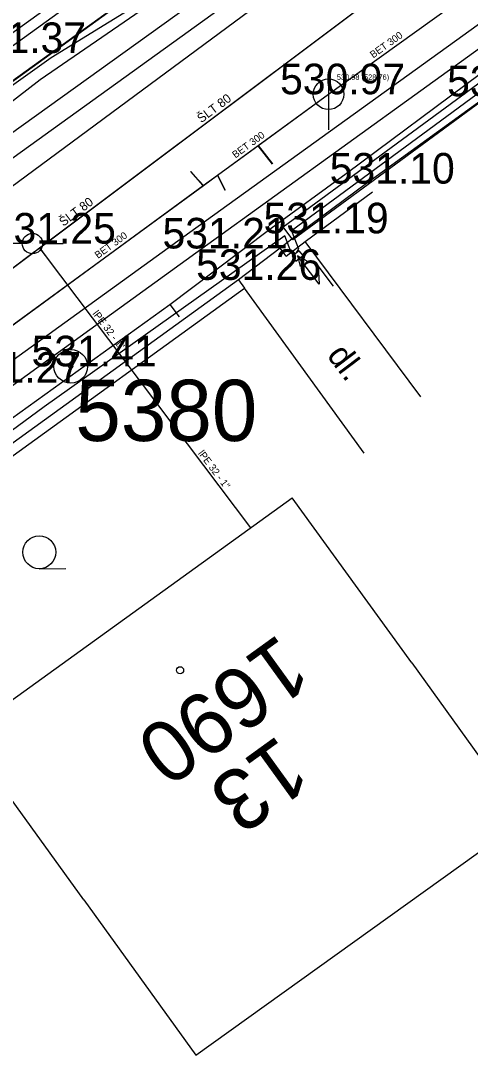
# Model space of a CAD drawing. Extents: x -668867 to -667827, y -1131943 to -1131019.
# Drawn here: x -668744.27 to -668733.24, y -1131426.29 to -1131400.93 of the extents above; entities that cross this region are included whole.
import ezdxf

# ---------------------------------------------------------------- set-up
doc = ezdxf.new("R2010")
doc.units = 0
for name, color, linetype in [('G_Bod_tecka', 7, 'Continuous'), ('G_Bod_vyska', 7, 'Continuous'), ('G_Bodove_pole', 7, 'Continuous'), ('G_Budovy-znacky', 7, 'Continuous'), ('G_Budovy_Objekty', 7, 'Continuous'), ('G_Cesty_Schody', 7, 'Continuous'), ('G_Cisla_orientacni', 7, 'Continuous'), ('G_Cisla_popisna', 7, 'Continuous'), ('G_Plochy_zpevnene', 7, 'Continuous'), ('G_Ploty', 7, 'Continuous'), ('G_Ploty_vstupy', 7, 'Continuous'), ('G_Popisy_povrchu', 7, 'Continuous'), ('G_Site-kanalizace', 7, 'Continuous'), ('G_Site-Rozvadece', 7, 'Continuous'), ('G_Site-vodovod', 7, 'Continuous'), ('G_Z_CHRANICKA-TEPLOVOD_kotovane', 7, 'Continuous'), ('G_Z_ELsilove_podz_kotovane', 7, 'Continuous'), ('G_Z_KANAL_podz_kotovane', 7, 'Continuous'), ('G_Z_PLYNY_podz_geodeticky', 7, 'Continuous'), ('G_Z_SPOJE_podz_geodeticky', 7, 'Continuous'), ('G_Z_SPOJE_podz_kotovane', 7, 'Continuous'), ('G_Z_SPOJE_podz_priblizne', 7, 'Continuous'), ('G_Z_VODA_podz_kotovane', 7, 'Continuous'), ('G_Zelen-Znacky', 7, 'Continuous'), ('Vrstva 10', 7, 'Continuous'), ('Vrstva 13', 7, 'Continuous'), ('Vrstva 17', 7, 'Continuous'), ('Vrstva 2', 7, 'Continuous'), ('Vrstva 25', 7, 'Continuous'), ('Vrstva 26', 7, 'Continuous'), ('Vrstva 3', 7, 'Continuous'), ('Vrstva 4', 7, 'Continuous'), ('Vrstva 6', 7, 'Continuous'), ('Vrstva 8', 7, 'Continuous')]:
    doc.layers.add(name, color=color, linetype=linetype)

msp = doc.modelspace()

# ---------------------------------------------------------------- linework, layer by layer
at = {"layer": 'G_Bod_tecka'}
for p, q in [((-668736.72, -1131402.73), (-668736.72, -1131402.73)), ((-668735.79, -1131404.92), (-668735.79, -1131404.92)), ((-668737.44, -1131406.14), (-668737.44, -1131406.14)), ((-668743.98, -1131406.39), (-668743.98, -1131406.39)), ((-668739.83, -1131406.51), (-668739.83, -1131406.51)), ((-668738.93, -1131407.28), (-668738.93, -1131407.28)), ((-668743.04, -1131409.4), (-668743.04, -1131409.4))]:
    msp.add_line(p, q, dxfattribs=at)
at = {"layer": 'G_Bodove_pole'}
for radius in [0.412, 0.05]:
    msp.add_circle((-668743.04, -1131409.4), radius, dxfattribs=at)
at = {"layer": 'G_Budovy-znacky'}
msp.add_circle((-668740.36, -1131416.85), 0.0875, dxfattribs=at)
at = {"layer": 'G_Budovy_Objekty'}
for p, q in [((-668745.65, -1131418.42), (-668737.61, -1131412.62)), ((-668734.68, -1131416.67), (-668737.61, -1131412.62)), ((-668734.68, -1131416.67), (-668731.92, -1131420.51)), ((-668742.72, -1131422.48), (-668745.65, -1131418.42)), ((-668739.97, -1131426.29), (-668731.92, -1131420.51)), ((-668742.72, -1131422.48), (-668739.97, -1131426.29))]:
    msp.add_line(p, q, dxfattribs=at)
at = {"layer": 'G_Cesty_Schody'}
for p, q in [((-668715.28, -1131383.29), (-668757.59, -1131413.74)), ((-668740.12, -1131406.11), (-668713.87, -1131387.19)), ((-668757.224, -1131418.469), (-668740.12, -1131406.11))]:
    msp.add_line(p, q, dxfattribs=at)
at = {"layer": 'G_Plochy_zpevnene'}
for p, q in [((-668715.57, -1131382.88), (-668757.89, -1131413.33)), ((-668739.83, -1131406.51), (-668713.58, -1131387.59)), ((-668735.85, -1131411.53), (-668738.78, -1131407.48))]:
    msp.add_line(p, q, dxfattribs=at)
msp.add_lwpolyline([(-668756.873, -1131418.834), (-668739.83, -1131406.51)], dxfattribs=at)
at = {"layer": 'G_Ploty'}
for p, q in [((-668742.28, -1131399.65), (-668744.86, -1131401.51)), ((-668742.13, -1131399.86), (-668744.71, -1131401.72)), ((-668735.79, -1131404.92), (-668737.44, -1131406.14)), ((-668737.29, -1131406.34), (-668735.64, -1131405.12)), ((-668737.44, -1131406.14), (-668737.91, -1131406.5)), ((-668737.76, -1131406.7), (-668737.91, -1131406.5)), ((-668737.76, -1131406.7), (-668737.29, -1131406.34)), ((-668734.46, -1131410.15), (-668737.29, -1131406.34)), ((-668738.93, -1131407.28), (-668749.12, -1131414.64)), ((-668738.93, -1131407.28), (-668738.78, -1131407.48)), ((-668748.97, -1131414.85), (-668738.78, -1131407.48))]:
    msp.add_line(p, q, dxfattribs=at)
at = {"layer": 'G_Ploty_vstupy'}
for p, q in [((-668732.83, -1131402.78), (-668735.79, -1131404.92)), ((-668737.91, -1131406.5), (-668738.93, -1131407.28))]:
    msp.add_line(p, q, dxfattribs=at)
at = {"layer": 'G_Site-kanalizace'}
msp.add_line((-668736.72, -1131402.355), (-668736.72, -1131403.605), dxfattribs=at)
msp.add_circle((-668736.72, -1131402.73), 0.375, dxfattribs=at)
at = {"layer": 'G_Site-Rozvadece'}
for p, q in [((-668736.949, -1131407.385), (-668737.48, -1131406.69)), ((-668737.244, -1131406.818), (-668737.48, -1131406.69)), ((-668737.48, -1131406.69), (-668737.419, -1131406.952)), ((-668736.598, -1131407.432), (-668736.977, -1131406.935)), ((-668736.977, -1131406.935), (-668736.949, -1131407.385))]:
    msp.add_line(p, q, dxfattribs=at)
msp.add_lwpolyline([(-668737.44, -1131406.57), (-668737.61, -1131406.7), (-668737.52, -1131406.82), (-668737.34, -1131406.68)], close=True, dxfattribs=at)
at = {"layer": 'G_Site-vodovod'}
for p, q in [((-668744.23, -1131406.39), (-668744.73, -1131406.39)), ((-668743.73, -1131406.39), (-668743.23, -1131406.39))]:
    msp.add_line(p, q, dxfattribs=at)
msp.add_circle((-668743.98, -1131406.39), 0.25, dxfattribs=at)
at = {"layer": 'G_Z_CHRANICKA-TEPLOVOD_kotovane'}
msp.add_lwpolyline([(-668737.829, -1131405.979), (-668731.738, -1131401.498), (-668731.501, -1131401.821), (-668737.592, -1131406.302)], close=True, dxfattribs=at)
at = {"layer": 'G_Z_ELsilove_podz_kotovane'}
for points in [[(-668761.242, -1131414.294), (-668758.43, -1131412.13), (-668758.21, -1131412), (-668758.21, -1131411.81), (-668758.19, -1131411.82), (-668758, -1131411.87), (-668757.46, -1131411.55), (-668748.36, -1131405.23), (-668745.77, -1131403.32), (-668745.4, -1131403.07), (-668741.67, -1131400.37), (-668741.88, -1131399.87), (-668741.89, -1131399.85), (-668741.49, -1131400.23), (-668733.81, -1131394.78), (-668733.29, -1131394.3), (-668731.24, -1131392.77), (-668725.68, -1131388.86), (-668725.4, -1131388.62), (-668725.61, -1131388.18), (-668725.61, -1131388.17), (-668725.24, -1131388.44), (-668724.41, -1131387.87), (-668723.31, -1131387.13)], [(-668761.235, -1131414.301), (-668758.52, -1131412.211), (-668758.84, -1131411.823), (-668758.819, -1131411.69), (-668758.686, -1131411.695), (-668758.353, -1131412.098), (-668757.561, -1131411.625), (-668757.704, -1131411.512), (-668757.71, -1131411.38), (-668757.58, -1131411.356), (-668757.384, -1131411.51), (-668748.37, -1131405.24), (-668745.78, -1131403.35), (-668745.41, -1131403.1), (-668744.52, -1131402.45), (-668741.6, -1131400.33), (-668733.83, -1131394.81), (-668733.384, -1131394.398), (-668733.998, -1131393.619)], [(-668731.62, -1131401.66), (-668737.627, -1131406.079), (-668737.458, -1131406.515), (-668737.52, -1131406.63), (-668737.644, -1131406.587), (-668737.794, -1131406.2), (-668743.69, -1131410.39), (-668748.58, -1131413.99), (-668752.16, -1131416.47), (-668753.31, -1131417.19), (-668756.295, -1131419.435)]]:
    msp.add_lwpolyline(points, dxfattribs=at)
at = {"layer": 'G_Z_KANAL_podz_kotovane'}
for p, q in [((-668738.45, -1131403.99), (-668738.1, -1131404.44)), ((-668739.79, -1131404.97), (-668740.1, -1131404.62)), ((-668739.44, -1131404.71), (-668739.26, -1131405.08))]:
    msp.add_line(p, q, dxfattribs=at)
for points in [[(-668736.72, -1131402.73), (-668724.39, -1131393.88), (-668722.55, -1131392.56), (-668710.43, -1131383.87), (-668709.28, -1131383.04), (-668709.09, -1131382.9), (-668707.24, -1131381.57)], [(-668757.657, -1131418.02), (-668755.08, -1131416.14), (-668747.04, -1131410.26), (-668745.38, -1131409.05), (-668739.79, -1131404.97), (-668739.44, -1131404.71), (-668738.45, -1131403.99), (-668736.72, -1131402.73)]]:
    msp.add_lwpolyline(points, dxfattribs=at)
at = {"layer": 'G_Z_PLYNY_podz_geodeticky'}
msp.add_lwpolyline([(-668759.629, -1131415.97), (-668755.51, -1131412.94), (-668755.01, -1131412.64), (-668748.41, -1131407.78), (-668748.11, -1131407.68), (-668745.83, -1131405.98), (-668738.65, -1131400.68), (-668735.63, -1131398.55), (-668733.62, -1131397.14), (-668728.96, -1131393.74)], dxfattribs=at)
at = {"layer": 'G_Z_SPOJE_podz_geodeticky'}
for points in [[(-668761.136, -1131414.404), (-668760.97, -1131414.27), (-668743.52, -1131401.83), (-668739.36, -1131399.26), (-668730.57, -1131392.83), (-668727.43, -1131390.78)], [(-668740.61, -1131407.88), (-668739.55, -1131407.08), (-668738.13, -1131406.01), (-668736.29, -1131404.67), (-668732.99, -1131402.22), (-668725.24, -1131396.68), (-668723.62, -1131395.47), (-668721.97, -1131394.38)], [(-668733.82, -1131395.31), (-668737.51, -1131397.91), (-668738.58, -1131398.79), (-668743.79, -1131402.38), (-668745.14, -1131403.41)], [(-668753, -1131416.86), (-668752.23, -1131416.38), (-668749.2, -1131414.06), (-668740.61, -1131407.88)], [(-668740.61, -1131407.88), (-668740.38, -1131408.19)]]:
    msp.add_lwpolyline(points, dxfattribs=at)
at = {"layer": 'G_Z_SPOJE_podz_kotovane'}
for points in [[(-668740.61, -1131407.88), (-668739.55, -1131407.08), (-668738.13, -1131406.01), (-668736.29, -1131404.67), (-668732.99, -1131402.22), (-668725.24, -1131396.68), (-668723.62, -1131395.47), (-668721.97, -1131394.38)], [(-668753, -1131416.86), (-668752.23, -1131416.38), (-668749.2, -1131414.06), (-668740.61, -1131407.88)], [(-668740.61, -1131407.88), (-668740.38, -1131408.19)]]:
    msp.add_lwpolyline(points, dxfattribs=at)
at = {"layer": 'G_Z_SPOJE_podz_priblizne'}
for points in [[(-668761.136, -1131414.404), (-668760.97, -1131414.27), (-668743.52, -1131401.83), (-668739.36, -1131399.26), (-668730.57, -1131392.83), (-668727.43, -1131390.78)], [(-668740.61, -1131407.88), (-668739.55, -1131407.08), (-668738.13, -1131406.01), (-668736.29, -1131404.67), (-668732.99, -1131402.22), (-668725.24, -1131396.68), (-668723.62, -1131395.47), (-668721.97, -1131394.38)], [(-668753, -1131416.86), (-668752.23, -1131416.38), (-668749.2, -1131414.06), (-668740.61, -1131407.88)], [(-668740.61, -1131407.88), (-668740.38, -1131408.19)]]:
    msp.add_lwpolyline(points, dxfattribs=at)
at = {"layer": 'G_Z_VODA_podz_kotovane'}
for points in [[(-668612.84, -1131311.89), (-668613.52, -1131312.39), (-668639.15, -1131330.75), (-668643.74, -1131334.04), (-668659.28, -1131345.16), (-668663.57, -1131348.23), (-668667.68, -1131351.59), (-668680.32, -1131360.39), (-668682.77, -1131361.98), (-668694.38, -1131370.3), (-668700.33, -1131374.56), (-668716.2, -1131385.93), (-668719.87, -1131388.55), (-668728.66, -1131395.15), (-668734.59, -1131399.59), (-668743.8, -1131406.5), (-668743.96, -1131406.62), (-668747.09, -1131408.97), (-668758.727, -1131416.908)], [(-668743.8, -1131406.5), (-668743.67, -1131406.68), (-668738.63, -1131413.36)]]:
    msp.add_lwpolyline(points, dxfattribs=at)
at = {"layer": 'G_Zelen-Znacky'}
msp.add_line((-668743.812, -1131414.36), (-668743.162, -1131414.357), dxfattribs=at)
msp.add_circle((-668743.812, -1131413.957), 0.403, dxfattribs=at)
at = {"layer": 'Vrstva 10'}
for points in [[(-668736.723, -1131402.729), (-668724.39, -1131393.881), (-668722.554, -1131392.563), (-668710.431, -1131383.866), (-668709.277, -1131383.038), (-668709.09, -1131382.904), (-668707.238, -1131381.575)], [(-668757.658, -1131418.018), (-668755.082, -1131416.137), (-668747.039, -1131410.263), (-668745.375, -1131409.048), (-668739.787, -1131404.966), (-668739.44, -1131404.713), (-668738.446, -1131403.987), (-668736.723, -1131402.729)]]:
    msp.add_lwpolyline(points, dxfattribs=at)
at = {"layer": 'Vrstva 13'}
for p, q in [((-668738.446, -1131403.987), (-668738.098, -1131404.438)), ((-668739.787, -1131404.966), (-668740.104, -1131404.621)), ((-668739.44, -1131404.713), (-668739.256, -1131405.077))]:
    msp.add_line(p, q, dxfattribs=at)
at = {"layer": 'Vrstva 17'}
msp.add_line((-668745.4, -1131403.07), (-668741.67, -1131400.37), dxfattribs=at)
at = {"layer": 'Vrstva 25'}
msp.add_lwpolyline([(-668743.804, -1131406.503), (-668743.671, -1131406.679), (-668738.632, -1131413.359)], dxfattribs=at)
at = {"layer": 'Vrstva 26'}
msp.add_lwpolyline([(-668612.843, -1131311.885), (-668613.516, -1131312.393), (-668639.148, -1131330.746), (-668643.745, -1131334.037), (-668659.276, -1131345.158), (-668663.568, -1131348.231), (-668667.684, -1131351.593), (-668680.32, -1131360.39), (-668682.771, -1131361.982), (-668694.383, -1131370.3), (-668700.33, -1131374.561), (-668716.198, -1131385.926), (-668719.869, -1131388.555), (-668728.661, -1131395.148), (-668734.589, -1131399.593), (-668743.804, -1131406.503), (-668743.957, -1131406.618), (-668747.094, -1131408.971), (-668758.727, -1131416.908)], dxfattribs=at)
at = {"layer": 'Vrstva 6'}
msp.add_line((-668743.671, -1131406.679), (-668743.671, -1131406.679), dxfattribs=at)
at = {"layer": 'Vrstva 8'}
msp.add_line((-668736.723, -1131402.729), (-668736.723, -1131402.729), dxfattribs=at)

# ---------------------------------------------------------------- texts
at = {"layer": 'G_Bod_vyska'}
for s, p in [('531.37', (-668745.732, -1131401.72)), ('530.97', (-668737.908, -1131402.73)), ('531.01', (-668733.812, -1131402.78)), ('531.10', (-668736.692, -1131404.92)), ('531.19', (-668738.313, -1131406.14)), ('531.25', (-668745.002, -1131406.39)), ('531.21', (-668740.791, -1131406.51)), ('531.26', (-668739.966, -1131407.28)), ('531.41', (-668744.001, -1131409.4)), ('531.27', (-668745.852, -1131409.8))]:
    msp.add_text(s, height=0.75, dxfattribs=at).set_placement(p)
at = {"layer": 'G_Bodove_pole'}
msp.add_text('5380', height=1.5, dxfattribs=at).set_placement((-668742.928, -1131411.23))
at = {"layer": 'G_Cisla_orientacni'}
msp.add_text('13', height=1.5, rotation=215.8522, dxfattribs=at).set_placement((-668737.933, -1131418.41))
at = {"layer": 'G_Cisla_popisna'}
msp.add_text('1690', height=1.5, rotation=215.8522, dxfattribs=at).set_placement((-668737.921, -1131415.926))
at = {"layer": 'G_Popisy_povrchu'}
msp.add_text('dl.', height=0.6, rotation=307.0121, dxfattribs=at).set_placement((-668736.778, -1131409.137))
at = {"layer": 'Vrstva 2'}
msp.add_text('530.98 (528.76)', height=0.13163, dxfattribs=at).set_placement((-668736.517, -1131402.376))
at = {"layer": 'Vrstva 3'}
for rotation, p in [(35.6547, (-668735.625, -1131401.854)), (36.1667, (-668739.003, -1131404.307)), (36.1115, (-668742.373, -1131406.768))]:
    msp.add_text('BET 300', height=0.1755, rotation=rotation, dxfattribs=at).set_placement(p)
at = {"layer": 'Vrstva 4'}
for s, height, rotation, p in [('ŠLT 80', 0.2194, 36.8699, (-668739.84, -1131403.443)), ('ŠLT 80', 0.2194, 36.8699, (-668743.223, -1131405.98)), ('lPE 32 - 1"', 0.17551, 307.0259, (-668742.514, -1131408.11)), ('lPE 32 - 1"', 0.17551, 307.0259, (-668739.928, -1131411.538))]:
    msp.add_text(s, height=height, rotation=rotation, dxfattribs=at).set_placement(p)

doc.saveas('drawing.dxf')
